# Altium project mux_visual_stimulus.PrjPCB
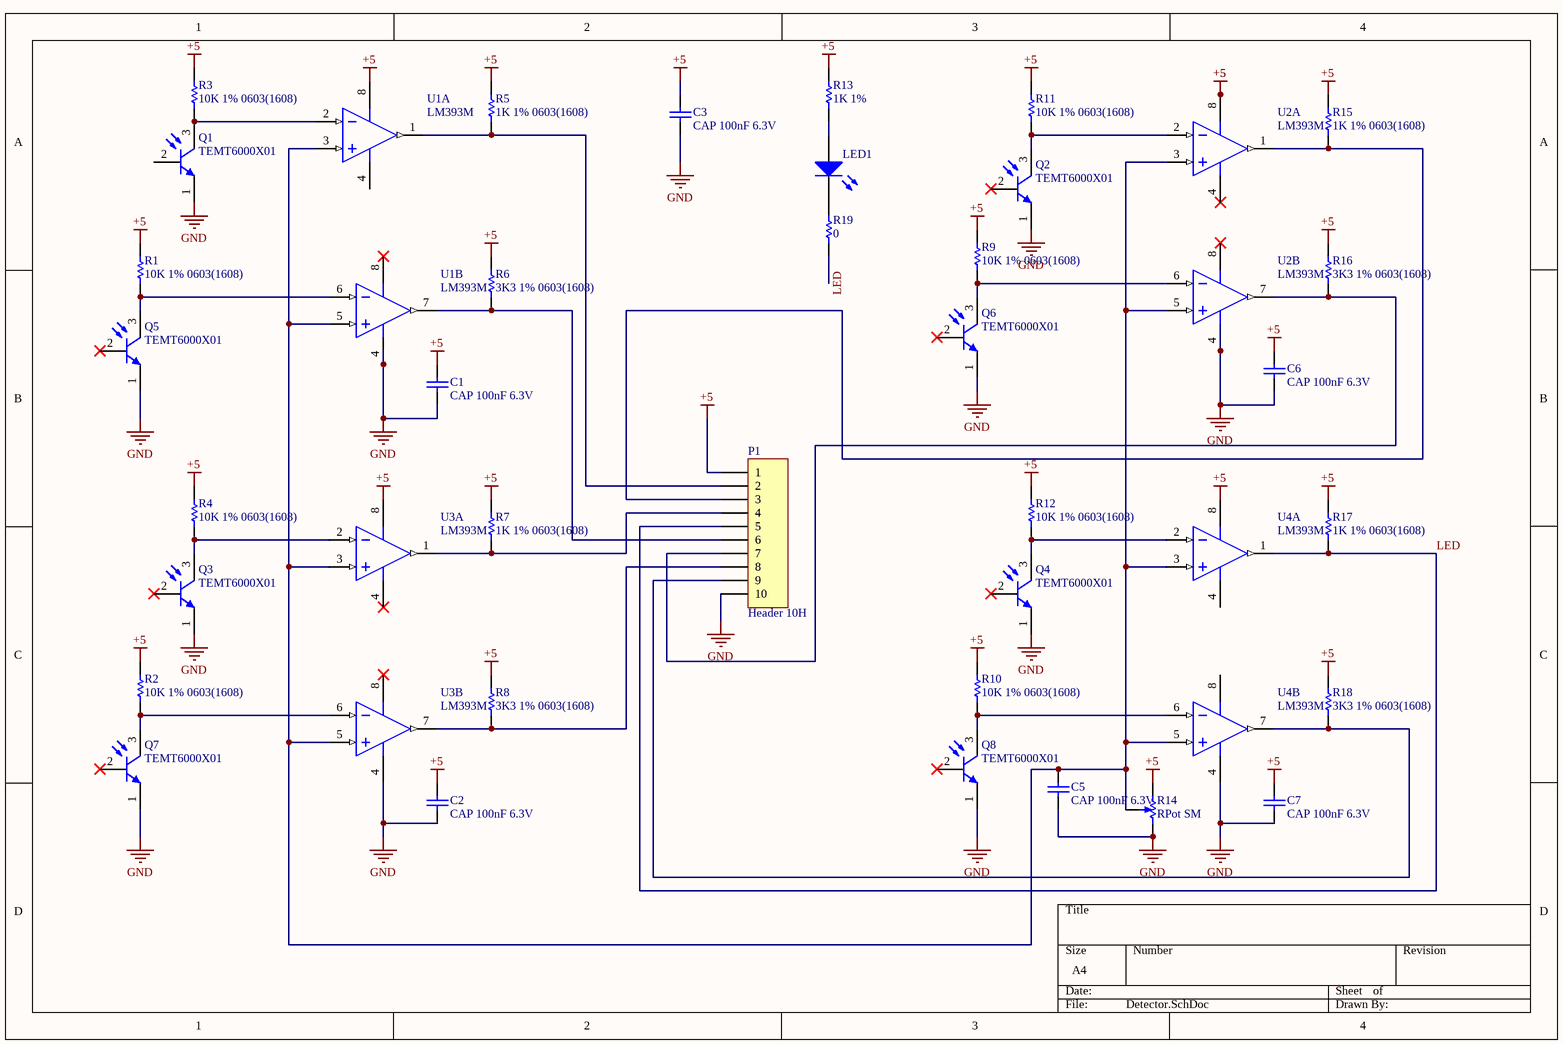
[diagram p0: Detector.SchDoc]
1 sheet, 39 parts. Net scope: global (net labels, ports and power ports of the same name join across sheets).
Board file: Visual_acqusation.PcbDoc

## Sheet Detector.SchDoc
size A4

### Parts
C1  CAP 100nF 6.3V  [CAPC0603(1608)100_N]
C2  CAP 100nF 6.3V  [CAPC0603(1608)100_N]
C3  CAP 100nF 6.3V  [CAPC0603(1608)100_N]
C5  CAP 100nF 6.3V  [CAPC0603(1608)100_N]
C6  CAP 100nF 6.3V  [CAPC0603(1608)100_N]
C7  CAP 100nF 6.3V  [CAPC0603(1608)100_N]
LED1  150060BS75000  [0603_A]  (value not drawn)
P1  Header 10H  [HDR1X10H]
Q1  TEMT6000X01  [VSIL-TEMT6000X01_V]
Q2  TEMT6000X01  [VSIL-TEMT6000X01_V]
Q3  TEMT6000X01  [VSIL-TEMT6000X01_V]
Q4  TEMT6000X01  [VSIL-TEMT6000X01_V]
Q5  TEMT6000X01  [VSIL-TEMT6000X01_V]
Q6  TEMT6000X01  [VSIL-TEMT6000X01_V]
Q7  TEMT6000X01  [VSIL-TEMT6000X01_V]
Q8  TEMT6000X01  [VSIL-TEMT6000X01_V]
R1  10K 1% 0603(1608)  [RESC0603(1608)_N]
R2  10K 1% 0603(1608)  [RESC0603(1608)_N]
R3  10K 1% 0603(1608)  [RESC0603(1608)_N]
R4  10K 1% 0603(1608)  [RESC0603(1608)_N]
R5  1K 1% 0603(1608)  [RESC0603(1608)_N]
R6  3K3 1% 0603(1608)  [RESC0603(1608)_N]
R7  1K 1% 0603(1608)  [RESC0603(1608)_N]
R8  3K3 1% 0603(1608)  [RESC0603(1608)_N]
R9  10K 1% 0603(1608)  [RESC0603(1608)_N]
R10  10K 1% 0603(1608)  [RESC0603(1608)_N]
R11  10K 1% 0603(1608)  [RESC0603(1608)_N]
R12  10K 1% 0603(1608)  [RESC0603(1608)_N]
R13  1K 1%  [RESC0603(1608)_N]
R14  RPot SM  [POT4MM-2]
R15  1K 1% 0603(1608)  [RESC0603(1608)_N]
R16  3K3 1% 0603(1608)  [RESC0603(1608)_N]
R17  1K 1% 0603(1608)  [RESC0603(1608)_N]
R18  3K3 1% 0603(1608)  [RESC0603(1608)_N]
R19  0  [RESC0603(1608)_N]
U1  LM393M  [D0008A_L]  (parts A,B of 2)
U2  LM393M  [D0008A_L]  (parts A,B of 2)
U3  LM393M  [D0008A_L]  (parts A,B of 2)
U4  LM393M  [D0008A_L]  (parts A,B of 2)

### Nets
+5: C1.2 C2.2 C3.2 C6.2 C7.2 P1.1 R1.2 R2.2 R3.2 R4.2 R5.2 R6.2 R7.2 R8.2 R9.2 R10.2 R11.2 R12.2 R13.2 R14.CCW(-) R15.2 R16.2 R17.2 R18.2 U1.8(V+) U2.8(V+) U3.8(V+) U4.8(V+)
GND: C1.1 C2.1 C3.1 C5.1 C6.1 C7.1 P1.10 Q1.1(E) Q2.1(E) Q3.1(E) Q4.1(E) Q5.1(E) Q6.1(E) Q7.1(E) Q8.1(E) R14.CW(+) U1.4(GND) U2.4(GND) U3.4(GND) U4.4(GND)
LED: P1.5 R17.1 R19.1 U4.1(OUTA)
NetC5_2: C5.2 R14.W U1.3(INA+) U1.5(INB+) U2.3(INA+) U2.5(INB+) U3.3(INA+) U3.5(INB+) U4.3(INA+) U4.5(INB+)
NetLED1_1: LED1.1(K) R19.2
NetLED1_2: LED1.2(A) R13.1
NetP1_2: P1.2 R5.1 U1.1(OUTA)
NetP1_3: P1.3 R15.1 U2.1(OUTA)
NetP1_4: P1.4 R7.1 U3.1(OUTA)
NetP1_6: P1.6 R6.1 U1.7(OUTB)
NetP1_7: P1.7 R16.1 U2.7(OUTB)
NetP1_8: P1.8 R8.1 U3.7(OUTB)
NetP1_9: P1.9 R18.1 U4.7(OUTB)
NetQ1_3: Q1.3(C) R3.1 U1.2(INA-)
NetQ2_3: Q2.3(C) R11.1 U2.2(INA-)
NetQ3_3: Q3.3(C) R4.1 U3.2(INA-)
NetQ4_3: Q4.3(C) R12.1 U4.2(INA-)
NetQ5_3: Q5.3(C) R1.1 U1.6(INB-)
NetQ6_3: Q6.3(C) R9.1 U2.6(INB-)
NetQ7_3: Q7.3(C) R2.1 U3.6(INB-)
NetQ8_3: Q8.3(C) R10.1 U4.6(INB-)

Not connected (* = marked no-connect by the designer): Q1 2(B); Q2 2(B)*; Q3 2(B)*; Q4 2(B)*; Q5 2(B)*; Q6 2(B)*; Q7 2(B)*; Q8 2(B)*

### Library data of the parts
C1-C3 C5-C7 = CMP-1035-02576-1: CAP 100nF 6.3V ±10% 0603 (1608 Metric) Thickness 1mm SMD; Tolerance: Â±10%; Case-Metric: 1608; Case-EIA: 0603
LED1 = CMP-1426-00003-1: SMD mono-color Chip LED, WL-SMCW, Blue; Manufacturer: Wuerth Elektronik
P1 = Header 10H: Header, 10-Pin, Right Angle
Q1-Q8 = CMP-1666-00035-1: Ambient Light Sensor / , 100 mW, -40 to 100 degC, 3-Pin SMD, RoHS, Tape and Reel; Nominal Vf: 2 V; Luminous Intensity: 54 mcd; Forward Current: 20 mA; Viewing Angle: 130 degrees; Lens Style: Diffused; Power Rating: 75 mW; Colour: Red; Case\Package: 0603
R1-R4 R9-R12 = CMP-1012-00623-1: 10K 0.1W 1% 0603 (1608 Metric)  SMD; Value: 10000.00 Ohm; Case-EIA: 0603; Case-Metric: 1608
R5-R8 R15-R18 = CMP-1012-00567-1: 3K3 0.1W 1% 0603 (1608 Metric)  SMD; Case-Metric: 1608; Value: 3300.00 Ohm; Case-EIA: 0603
R13 R19 = CMP-1012-00510-1: 1K 0.1W 1% 0603 (1608 Metric)  SMD; Case-Metric: 1608; Case-EIA: 0603; Value: 1000.00 Ohm
R14 = RPot SM: Square Trimming Potentiometer
U1-U4 = CMP-0055-00682-3: Low Power Low Offset Voltage Dual Comparator, 8-pin Narrow SOIC; Manufacturer: Texas Instruments; CompType: Amplifiers; PowerWise: N; PackageTopMarking: NSZXTT*LM*393M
